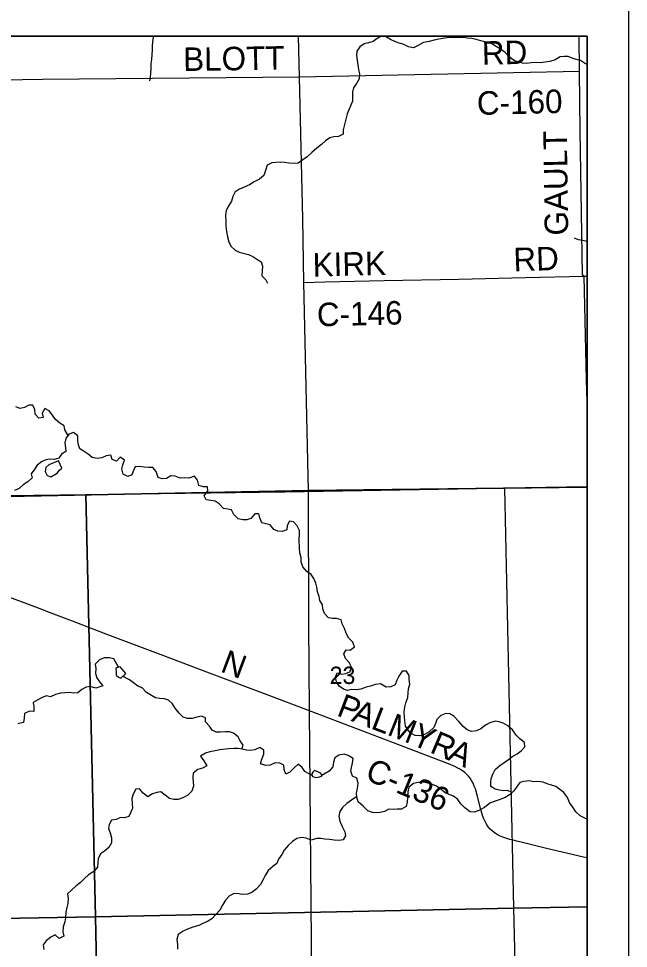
# Model space of a CAD drawing. Extents: x 0 to 34, y 0 to 22.
# Drawn here: x 8.87 to 10.344, y 17.72 to 19.966 of the extents above; entities that cross this region are included whole.
import ezdxf

# ---------------------------------------------------------------- set-up
doc = ezdxf.new("R2010")
doc.units = 0
for name, color, linetype in [('GM_X_Corporation', 7, 'Continuous'), ('GM_X_County_Road', 7, 'Continuous'), ('GM_X_County_Road_Text', 7, 'Continuous'), ('GM_X_Minor_Lake', 7, 'Continuous'), ('GM_X_Minor_River', 7, 'Continuous'), ('GM_X_Section_Text', 7, 'Continuous'), ('GM_X_State_Route', 7, 'Continuous'), ('GM_X_Township_Road', 7, 'Continuous'), ('GM_X_Township_Road_Text', 7, 'Continuous'), ('SH_Data', 7, 'Continuous')]:
    doc.layers.add(name, color=color, linetype=linetype)

msp = doc.modelspace()

# ---------------------------------------------------------------- linework, layer by layer
at = {"layer": 'GM_X_Corporation'}
for points in [[(10.2438, 18.8341), (10.2438, 19.9239), (6.9951, 19.9239), (7.0002, 19.6505), (7.0062, 19.3415), (7.0072, 19.2641), (7.0169, 18.7868), (8.0146, 18.8), (8.2239, 18.8028), (8.7622, 18.8099), (9.5705, 18.8263)], [(10.0443, 18.8318), (10.0662, 17.8169), (9.0559, 17.7965), (9.0322, 18.8161), (9.5131, 18.823), (10.0245, 18.8315)], [(10.2438, 17.8207), (10.2438, 18.8353), (10.0443, 18.8318), (10.0662, 17.8169)], [(9.0322, 18.8161), (9.0559, 17.7965), (8.0487, 17.7782), (8.025, 18.8024), (8.5284, 18.8103)], [(10.0662, 17.8169), (10.0909, 16.801), (9.0769, 16.778), (9.0559, 17.7965)], [(10.2438, 16.8039), (10.2438, 17.8207), (10.0662, 17.8169), (10.0909, 16.801)], [(8.0487, 17.7782), (9.0559, 17.7965), (9.0769, 16.778), (8.0702, 16.7576)]]:
    msp.add_lwpolyline(points, close=True, dxfattribs=at)
msp.add_lwpolyline([(10.2438, 13.7323), (10.2438, 18.8341), (9.5705, 18.8263), (8.7622, 18.8099), (8.2239, 18.8028), (8.0146, 18.8), (7.0169, 18.7868), (7.0182, 18.7109), (7.0206, 18.595), (7.0233, 18.4737), (7.0259, 18.3381), (7.0286, 18.1986), (7.0307, 18.0432), (7.0341, 17.8886), (7.0383, 17.6784), (7.0382, 17.6446), (7.0667, 16.1653), (7.068, 16.109), (7.0714, 16.0063)], dxfattribs=at)
at = {"layer": 'GM_X_County_Road'}
msp.add_line((10.2258, 19.8383), (9.5487, 19.825), dxfattribs=at)
for points in [[(9.5487, 19.825), (8.9278, 19.8189), (8.7335, 19.8158)], [(9.5594, 19.3287), (9.6101, 19.3301), (9.6821, 19.3318), (9.7539, 19.3333), (9.9338, 19.3369), (10.094, 19.3405), (10.2365, 19.3437), (10.2438, 19.3438)], [(10.2438, 19.0407), (10.2425, 19.0936), (10.2365, 19.3437)], [(9.5729, 18.2936), (9.4709, 18.3328), (9.3316, 18.385), (9.2144, 18.429), (9.0854, 18.4774), (9.0003, 18.5102), (8.9679, 18.5225), (8.9443, 18.5317), (8.9219, 18.5399), (8.8156, 18.5798)], [(9.8858, 18.1745), (9.776, 18.2165), (9.5729, 18.2936)], [(10.0848, 17.9764), (10.0742, 17.979), (10.0653, 17.9812), (10.0572, 17.9832), (10.0497, 17.9853), (10.0404, 17.9883), (10.0321, 17.992), (10.0251, 17.9956), (10.0194, 17.9998), (10.0144, 18.0039), (10.0098, 18.0083), (10.0052, 18.0139), (10.0008, 18.0201), (9.9973, 18.0262), (9.9943, 18.0333), (9.9915, 18.0412), (9.9875, 18.0552), (9.9786, 18.0897), (9.974, 18.1055), (9.9714, 18.1122), (9.9684, 18.1189), (9.9646, 18.1254), (9.9614, 18.1309), (9.9576, 18.1357), (9.9533, 18.1402), (9.9484, 18.1447), (9.943, 18.1487), (9.9378, 18.1522), (9.9318, 18.1556), (9.9246, 18.1593), (9.9089, 18.1657), (9.8858, 18.1745)], [(10.2438, 17.9389), (10.2352, 17.9407), (10.1456, 17.9615), (10.0848, 17.9764)]]:
    msp.add_lwpolyline(points, dxfattribs=at)
at = {"layer": 'GM_X_Minor_Lake'}
for points in [[(8.9666, 18.8974), (8.9428, 18.888), (8.9361, 18.8818), (8.9343, 18.8719), (8.939, 18.8625), (8.9481, 18.8588), (8.9636, 18.8677), (8.9688, 18.875), (8.9748, 18.88)], [(8.9748, 18.88), (8.9666, 18.8974)], [(9.1289, 18.3838), (9.1158, 18.4004), (9.109, 18.3984), (9.1048, 18.3964), (9.1057, 18.3877), (9.1062, 18.3797), (9.1116, 18.3749), (9.1169, 18.373)], [(9.1169, 18.373), (9.1289, 18.3838)], [(9.6004, 18.1422), (9.5977, 18.1441), (9.5913, 18.1471), (9.5855, 18.1493), (9.581, 18.1454), (9.5784, 18.142), (9.5796, 18.1363), (9.5865, 18.133), (9.5941, 18.1334), (9.6032, 18.1362)], [(9.6032, 18.1362), (9.6022, 18.1395), (9.601, 18.1414), (9.6004, 18.1422)]]:
    msp.add_lwpolyline(points, dxfattribs=at)
at = {"layer": 'GM_X_Minor_River'}
for points in [[(9.1958, 19.9239), (9.1955, 19.9215), (9.1934, 19.9101), (9.1928, 19.8998), (9.1925, 19.8899), (9.1923, 19.8796), (9.1913, 19.8675), (9.1895, 19.858), (9.1893, 19.8458), (9.1891, 19.8355), (9.1881, 19.8241), (9.1866, 19.8161)], [(10.2438, 19.8563), (10.2399, 19.8571), (10.228, 19.8649), (10.2177, 19.8671), (10.2078, 19.8704), (10.1983, 19.8745), (10.1888, 19.8743), (10.1789, 19.8738), (10.1669, 19.8665), (10.154, 19.8629), (10.143, 19.8609), (10.1313, 19.8596), (10.1183, 19.8598), (10.1085, 19.8597), (10.0986, 19.8573), (10.0876, 19.8587), (10.0781, 19.8616), (10.0686, 19.8641), (10.0555, 19.8742), (10.0463, 19.884), (10.0348, 19.8926), (10.0241, 19.8985), (10.0134, 19.9056), (10.0004, 19.9089), (9.9871, 19.9125), (9.976, 19.9158), (9.9654, 19.9183), (9.9547, 19.919), (9.9445, 19.9204), (9.9346, 19.9202), (9.9225, 19.9197), (9.9115, 19.9207), (9.9005, 19.9191), (9.8857, 19.9162), (9.8747, 19.9138), (9.8619, 19.9106), (9.8482, 19.9086), (9.8354, 19.9008), (9.8241, 19.8957), (9.8127, 19.8982), (9.7993, 19.9042), (9.7894, 19.9071), (9.7795, 19.9108), (9.7688, 19.9159), (9.7569, 19.923), (9.7471, 19.9237), (9.7369, 19.9178), (9.7267, 19.9109), (9.7154, 19.9073), (9.7052, 19.9049), (9.695, 19.8979), (9.6872, 19.8876), (9.6869, 19.8769), (9.6886, 19.8659), (9.6895, 19.8542), (9.6912, 19.8428), (9.6936, 19.8318), (9.693, 19.8204), (9.6863, 19.8097), (9.6792, 19.7993), (9.677, 19.7883), (9.6768, 19.7784), (9.6766, 19.767), (9.6733, 19.7567), (9.6692, 19.7472), (9.6641, 19.7357), (9.659, 19.717), (9.6568, 19.7075), (9.6547, 19.6976), (9.6544, 19.6873), (9.6431, 19.6815), (9.6321, 19.6802), (9.6219, 19.6782), (9.6117, 19.6712), (9.602, 19.6624), (9.5911, 19.6531), (9.5783, 19.6423), (9.5678, 19.6323), (9.5573, 19.6246)], [(9.5573, 19.6246), (9.5453, 19.6169), (9.5358, 19.6164), (9.5232, 19.6173), (9.513, 19.6187), (9.5027, 19.619), (9.4917, 19.6185), (9.4819, 19.618), (9.4709, 19.6121), (9.4665, 19.5988), (9.4625, 19.5873), (9.452, 19.5785), (9.4392, 19.5722), (9.4279, 19.5645), (9.4154, 19.559), (9.4041, 19.554), (9.3932, 19.5477), (9.3876, 19.5363), (9.3844, 19.5252), (9.378, 19.5145), (9.3717, 19.5023), (9.3704, 19.4909), (9.3706, 19.4768), (9.3711, 19.4646), (9.3724, 19.4521), (9.3752, 19.4392), (9.3784, 19.4271), (9.3831, 19.4165), (9.3935, 19.4068), (9.403, 19.402), (9.4259, 19.3962), (9.4358, 19.3913), (9.4458, 19.385), (9.4565, 19.3783), (9.4596, 19.3677), (9.4583, 19.3563), (9.4581, 19.3445), (9.4673, 19.3347), (9.4716, 19.3272)], [(10.2438, 19.4274), (10.2435, 19.4274), (10.234, 19.4304), (10.2233, 19.4321), (10.2134, 19.4354)], [(8.9897, 18.9594), (8.982, 18.9728), (8.9799, 18.9827), (8.9696, 18.9886), (8.9592, 18.998), (8.9523, 19.0082), (8.9438, 19.0187), (8.9335, 19.0243), (8.9271, 19.0132), (8.9296, 19.0026), (8.919, 19.0009), (8.9101, 19.0107), (8.9092, 19.0217), (8.9041, 19.0319), (8.8946, 19.0322), (8.8845, 19.0263), (8.8735, 19.0239), (8.8636, 19.028)], [(9.5964, 18.57), (9.5921, 18.581), (9.5908, 18.5927), (9.588, 18.6026), (9.5837, 18.6132), (9.5767, 18.6229), (9.5668, 18.6308), (9.5571, 18.6421), (9.5532, 18.6538), (9.5527, 18.6633), (9.5499, 18.6754), (9.5486, 18.6872), (9.5483, 18.7077), (9.5485, 18.7195), (9.5492, 18.7298), (9.5433, 18.7411), (9.5345, 18.7508), (9.5246, 18.7519), (9.5194, 18.7415), (9.518, 18.7309), (9.5067, 18.7273), (9.4964, 18.7276), (9.4869, 18.7317), (9.478, 18.7433), (9.4677, 18.7459), (9.4578, 18.748), (9.4531, 18.7597), (9.4503, 18.7696), (9.4409, 18.7695), (9.4315, 18.7583), (9.4213, 18.7555), (9.4118, 18.7554), (9.4008, 18.758), (9.3904, 18.7681), (9.3849, 18.7794), (9.3754, 18.7808), (9.3655, 18.7826), (9.3551, 18.7942), (9.3452, 18.8002), (9.3342, 18.8016), (9.3235, 18.8034), (9.3188, 18.8136), (9.327, 18.8254), (9.3265, 18.8349), (9.317, 18.8352), (9.3056, 18.8385), (9.3024, 18.851), (9.2954, 18.8608), (9.2814, 18.856), (9.27, 18.8567), (9.2606, 18.8562), (9.2484, 18.861), (9.2377, 18.8616), (9.2272, 18.8554), (9.2166, 18.8541), (9.207, 18.8574), (9.2023, 18.8718), (9.1942, 18.8819), (9.1839, 18.8818), (9.1733, 18.8821), (9.1619, 18.8842), (9.1516, 18.8837), (9.1476, 18.8742), (9.1436, 18.8639), (9.1337, 18.8599), (9.123, 18.8659), (9.1191, 18.8784), (9.122, 18.8879), (9.1256, 18.8993), (9.1157, 18.9068), (9.1063, 18.8972), (9.0964, 18.9009), (9.0932, 18.9115), (9.0815, 18.9102), (9.0709, 18.9048), (9.0595, 18.9035), (9.0481, 18.906), (9.0381, 18.9139), (9.0282, 18.9202), (9.0182, 18.9269), (9.0143, 18.939), (9.0134, 18.9485), (9.0129, 18.9584), (9.0025, 18.9666), (8.9916, 18.9619), (8.9838, 18.9516), (8.9816, 18.9409), (8.9833, 18.9295), (8.9838, 18.92), (8.9736, 18.9142), (8.9673, 18.9042), (8.9559, 18.9014), (8.9453, 18.9017), (8.9355, 18.9001), (8.9253, 18.895), (8.9151, 18.8877), (8.9096, 18.8781), (8.9006, 18.8666), (8.903, 18.8564), (8.8921, 18.8471), (8.8812, 18.8397)], [(8.8812, 18.8397), (8.8711, 18.8309), (8.8601, 18.8262)], [(10.0621, 18.0962), (10.0515, 18.101), (10.0416, 18.1009), (10.0314, 18.1019), (10.0218, 18.1048), (10.0115, 18.1108), (10.011, 18.1203), (10.0124, 18.1302), (10.0161, 18.1405), (10.022, 18.1519), (10.0329, 18.162), (10.0438, 18.1689), (10.0543, 18.1763), (10.0641, 18.184), (10.0747, 18.1898), (10.0848, 18.1972), (10.0934, 18.2068), (10.0925, 18.217), (10.0818, 18.2264), (10.0722, 18.2354), (10.0633, 18.2482), (10.0521, 18.2572), (10.0411, 18.2639), (10.0315, 18.2676), (10.0216, 18.269), (10.0092, 18.2646), (9.9982, 18.2596), (9.987, 18.2503), (9.9768, 18.2456), (9.9643, 18.2443), (9.954, 18.248), (9.9444, 18.2559), (9.9336, 18.2679), (9.922, 18.281), (9.9121, 18.2866), (9.9026, 18.2876), (9.8905, 18.2822), (9.8804, 18.2729), (9.8775, 18.2634), (9.8734, 18.2539), (9.8626, 18.2427), (9.8509, 18.2365), (9.8395, 18.2337), (9.8285, 18.2339), (9.8166, 18.241), (9.8054, 18.2564), (9.8038, 18.2693), (9.8029, 18.2796), (9.8016, 18.2906), (9.8033, 18.3032), (9.8055, 18.3134), (9.811, 18.3264), (9.8116, 18.3374), (9.8126, 18.3473), (9.8159, 18.358), (9.8142, 18.3694), (9.8141, 18.3789), (9.8075, 18.3895), (9.7973, 18.3893), (9.7891, 18.3778), (9.7839, 18.3679), (9.7799, 18.3564), (9.77, 18.3521), (9.7583, 18.3512), (9.7445, 18.359), (9.7324, 18.3578), (9.7207, 18.3531), (9.7097, 18.3514), (9.6969, 18.3459), (9.6859, 18.3447), (9.6749, 18.3453), (9.665, 18.3433), (9.6551, 18.3458), (9.6448, 18.3533), (9.6382, 18.3638), (9.6358, 18.3752), (9.6402, 18.3859), (9.6501, 18.3826), (9.6607, 18.3842), (9.6709, 18.3878), (9.6745, 18.3992), (9.6687, 18.4106), (9.6602, 18.4203), (9.6563, 18.4313), (9.6619, 18.4409), (9.6717, 18.4406), (9.6815, 18.4487), (9.6779, 18.4601), (9.6679, 18.4694), (9.6617, 18.4815), (9.6574, 18.4925), (9.6523, 18.5038), (9.6495, 18.514), (9.6385, 18.5166), (9.6286, 18.5172), (9.6187, 18.5182), (9.6091, 18.5287), (9.6052, 18.5401), (9.6046, 18.55), (9.5977, 18.5605), (9.5964, 18.57)], [(9.1116, 18.3991), (9.1, 18.4196), (9.0893, 18.4217), (9.0772, 18.4216), (9.0659, 18.4172), (9.055, 18.4065), (9.057, 18.3959), (9.056, 18.3841), (9.0592, 18.3735), (9.0654, 18.3637), (9.0739, 18.3539), (9.0565, 18.3487), (9.0432, 18.3528), (9.0329, 18.3511), (9.0228, 18.3453), (9.013, 18.3372), (9.0035, 18.3363), (8.9933, 18.3381), (8.9826, 18.3376), (8.9709, 18.3367), (8.9595, 18.3331), (8.9475, 18.328), (8.9372, 18.3302), (8.927, 18.3263), (8.9164, 18.3201), (8.9055, 18.3142), (8.9072, 18.3032), (8.9069, 18.2922), (8.8963, 18.2932), (8.8842, 18.2877), (8.8832, 18.276), (8.8815, 18.2657), (8.8678, 18.2621)], [(9.4098, 18.2012), (9.4124, 18.211), (9.4058, 18.2215), (9.4008, 18.2314), (9.3897, 18.2396), (9.3801, 18.2429), (9.3703, 18.2432), (9.3577, 18.2419), (9.3475, 18.2425), (9.3376, 18.2473), (9.331, 18.2571), (9.3214, 18.2669), (9.3216, 18.2768), (9.3121, 18.2808), (9.3011, 18.2784), (9.2897, 18.2756), (9.2784, 18.2751), (9.2681, 18.2788), (9.2577, 18.2881), (9.2484, 18.3006), (9.2422, 18.3111), (9.2322, 18.3194), (9.2227, 18.3227), (9.2113, 18.3233), (9.201, 18.3254), (9.1911, 18.3306), (9.1789, 18.3385), (9.1685, 18.3494), (9.1578, 18.3538), (9.1478, 18.3613), (9.1382, 18.3684), (9.1283, 18.3736), (9.1222, 18.3778)], [(9.5794, 18.1374), (9.5616, 18.1475), (9.5554, 18.1573), (9.5459, 18.1651), (9.5357, 18.1563), (9.5256, 18.1455), (9.5158, 18.1412), (9.5119, 18.1522), (9.511, 18.1624), (9.501, 18.1676), (9.4904, 18.1679), (9.4776, 18.1628), (9.4673, 18.1615), (9.4548, 18.1655), (9.4576, 18.177), (9.4624, 18.1892), (9.4627, 18.1987), (9.4531, 18.205), (9.4407, 18.1996), (9.4308, 18.1983), (9.4205, 18.1989), (9.4103, 18.2011), (9.4, 18.2025), (9.3905, 18.2031), (9.3776, 18.2022), (9.3564, 18.1997), (9.3454, 18.1976), (9.3322, 18.1944), (9.322, 18.1917), (9.3095, 18.1843), (9.318, 18.173), (9.325, 18.1613), (9.3145, 18.1551), (9.3035, 18.1519), (9.2922, 18.143), (9.2908, 18.1328), (9.2917, 18.1221), (9.2926, 18.1119), (9.2886, 18.1001), (9.2792, 18.0904), (9.2672, 18.0835), (9.2558, 18.0799), (9.2452, 18.0794), (9.2345, 18.0819), (9.2246, 18.0905), (9.2138, 18.098), (9.204, 18.0967), (9.1934, 18.0932), (9.1825, 18.0862), (9.1714, 18.0952), (9.1625, 18.1054), (9.153, 18.1045), (9.1467, 18.0926), (9.1435, 18.0819), (9.1444, 18.0702), (9.1449, 18.0588), (9.1412, 18.0492), (9.1368, 18.0386), (9.1258, 18.035), (9.1163, 18.036), (9.1061, 18.0313), (9.0948, 18.0293), (9.0885, 18.0193), (9.0874, 18.0098), (9.091, 17.9992), (9.0942, 17.9871), (9.0947, 17.975), (9.0877, 17.9635), (9.0779, 17.955), (9.0681, 17.948), (9.0622, 17.9362), (9.0616, 17.9267), (9.0606, 17.916), (9.052, 17.9053), (9.0392, 17.8975), (9.029, 17.8887), (9.0193, 17.8791), (9.0095, 17.871), (8.9983, 17.861), (8.9881, 17.8521), (8.9898, 17.8415), (8.9892, 17.8285), (8.9867, 17.819), (8.9845, 17.8072), (8.9832, 17.7939), (8.9818, 17.7844), (8.9778, 17.7718), (8.9772, 17.76), (8.9792, 17.7498), (8.9679, 17.7436), (8.9583, 17.7529), (8.9481, 17.7467), (8.9365, 17.7379), (8.929, 17.7283), (8.931, 17.7173)], [(10.2438, 18.0318), (10.2383, 18.0342), (10.2269, 18.0405), (10.2165, 18.0498), (10.2092, 18.0608), (10.2014, 18.0721), (10.1967, 18.0846), (10.1874, 18.0962), (10.1779, 18.1037), (10.1683, 18.1108), (10.1477, 18.1174), (10.1374, 18.1214), (10.1249, 18.1228), (10.1146, 18.1227), (10.104, 18.1248), (10.0911, 18.1232), (10.0812, 18.1204), (10.073, 18.1093), (10.0659, 18.0997), (10.0562, 18.0908), (10.0456, 18.0846), (10.0313, 18.0787), (10.0196, 18.0748), (10.0086, 18.0705), (9.9962, 18.0601), (9.9827, 18.0527), (9.9721, 18.0491), (9.9611, 18.0501), (9.9484, 18.0595), (9.9388, 18.0689), (9.9315, 18.0798), (9.9207, 18.0873), (9.9108, 18.0917), (9.9013, 18.0961), (9.8913, 18.1036), (9.8798, 18.1118), (9.8703, 18.1155), (9.8592, 18.1188), (9.8482, 18.1217), (9.8353, 18.1204), (9.8243, 18.118), (9.8134, 18.1091), (9.8105, 18.0981), (9.8103, 18.084), (9.8093, 18.0741), (9.8068, 18.0627), (9.7951, 18.0565), (9.7849, 18.056), (9.775, 18.0555), (9.7651, 18.0561), (9.7546, 18.0507), (9.744, 18.0479), (9.7345, 18.0477), (9.725, 18.048), (9.7139, 18.0521), (9.7024, 18.0633), (9.6909, 18.0742), (9.6873, 18.0855), (9.6868, 18.095), (9.6893, 18.1065), (9.6903, 18.119), (9.6871, 18.1311), (9.6768, 18.1363), (9.6729, 18.1477), (9.6743, 18.1572), (9.6772, 18.1671), (9.6785, 18.1785), (9.6667, 18.186), (9.6571, 18.1889), (9.6443, 18.1865), (9.6341, 18.1806), (9.6312, 18.17), (9.6291, 18.1582), (9.6205, 18.1478), (9.6107, 18.1424), (9.6027, 18.1376)], [(9.6872, 18.087), (9.6745, 18.0782), (9.6632, 18.0697), (9.6531, 18.0604), (9.6464, 18.0505), (9.6443, 18.039), (9.6467, 18.0273), (9.6522, 18.0148), (9.6588, 18.0016), (9.6597, 17.9917), (9.6541, 17.9818), (9.6446, 17.9809), (9.6329, 17.9815), (9.6211, 17.9829), (9.6104, 17.9835), (9.6005, 17.9857), (9.5903, 17.9852), (9.5774, 17.9816), (9.5652, 17.9864), (9.5546, 17.9878), (9.5421, 17.9857), (9.5323, 17.9784), (9.5211, 17.9684), (9.5121, 17.9573), (9.5058, 17.9466), (9.4983, 17.9358), (9.4943, 17.9251), (9.4845, 17.9174), (9.4729, 17.9078), (9.4658, 17.8963), (9.461, 17.886), (9.4543, 17.8741), (9.4438, 17.8633), (9.4333, 17.8549), (9.4231, 17.8506), (9.411, 17.8504), (9.4011, 17.8518), (9.3912, 17.8524), (9.3795, 17.847), (9.3702, 17.8366), (9.3631, 17.8244), (9.3564, 17.8121), (9.337, 17.7914), (9.3268, 17.7852), (9.3151, 17.7801), (9.3053, 17.775), (9.2909, 17.7711), (9.2785, 17.766), (9.2679, 17.7613), (9.2555, 17.7535), (9.2522, 17.7413), (9.2539, 17.7292), (9.254, 17.7178)]]:
    msp.add_lwpolyline(points, dxfattribs=at)
at = {"layer": 'GM_X_State_Route'}
for points in [[(9.5594, 19.3287), (9.557, 19.4822), (9.5487, 19.825), (9.5467, 19.9239)], [(9.5875, 16.7735), (9.581, 17.3663), (9.5729, 18.2936), (9.5715, 18.5043), (9.5707, 18.8257), (9.5594, 19.3287)]]:
    msp.add_lwpolyline(points, dxfattribs=at)
at = {"layer": 'GM_X_Township_Road'}
msp.add_line((10.2258, 19.8383), (10.2248, 19.9239), dxfattribs=at)
msp.add_lwpolyline([(10.2365, 19.3437), (10.2327, 19.3464), (10.2293, 19.5475), (10.2274, 19.6947), (10.2258, 19.8383)], dxfattribs=at)
at = {"layer": 'SH_Data'}
for p, q in [((10.3438, 20.0239), (10.3438, 13.0239)), ((3.4438, 19.9239), (10.2438, 19.9239)), ((10.2438, 19.9239), (10.2438, 13.1239))]:
    msp.add_line(p, q, dxfattribs=at)

# ---------------------------------------------------------------- texts
at = {"layer": 'GM_X_County_Road_Text'}
for s, height, rotation, p in [('RD', 0.05682, 1.4806, (9.9903, 19.8543)), ('BLOTT', 0.05682, 0.8554, (9.2681, 19.8394)), ('C-160', 0.05682, 1.3774, (9.9783, 19.7333)), ('RD', 0.05682, 1.9738, (10.0668, 19.3553)), ('KIRK', 0.05682, 1.4032, (9.5812, 19.3428)), ('C-146', 0.05682, 1.3763, (9.5916, 19.2225)), ('N', 0.0568, 339.444, (9.3553, 18.3894)), ('P', 0.0568, 339.0219, (9.6363, 18.2835)), ('A', 0.0568, 339.0219, (9.6721, 18.2698)), ('L', 0.0568, 338.996, (9.7188, 18.2519)), ('M', 0.0568, 338.2194, (9.7583, 18.2367)), ('Y', 0.0568, 337.054, (9.8153, 18.214)), ('R', 0.0568, 336.8721, (9.8613, 18.1945)), ('A', 0.0568, 335.6935, (9.9039, 18.1763)), ('C-136', 0.05682, 337.2959, (9.7046, 18.1289))]:
    msp.add_text(s, height=height, rotation=rotation, dxfattribs=at).set_placement(p)
at = {"layer": 'GM_X_Section_Text'}
msp.add_text('23', height=0.04186, rotation=0, dxfattribs=at).set_placement((9.6217, 18.3587))
at = {"layer": 'GM_X_Township_Road_Text'}
msp.add_text('GAULT', height=0.05682, rotation=90.813, dxfattribs=at).set_placement((10.1985, 19.4425))

doc.saveas('drawing.dxf')
